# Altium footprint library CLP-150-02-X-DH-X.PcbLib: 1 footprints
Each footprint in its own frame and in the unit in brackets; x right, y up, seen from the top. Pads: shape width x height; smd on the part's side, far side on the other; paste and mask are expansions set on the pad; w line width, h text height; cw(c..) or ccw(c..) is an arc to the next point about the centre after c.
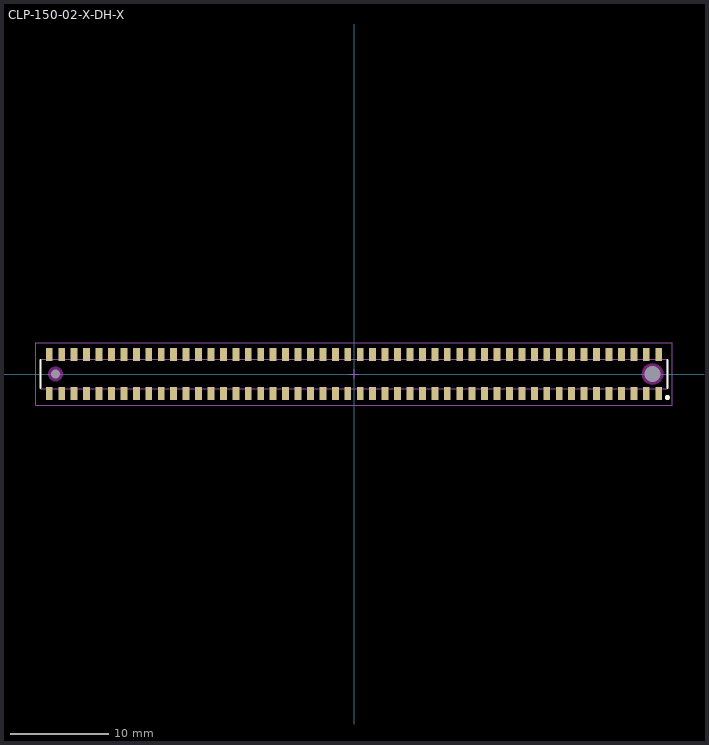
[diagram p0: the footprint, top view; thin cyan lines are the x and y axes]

## CLP-150-02-X-DH-X [mm] "1.27mm pitch, 100 pin, socket strip; low profile, vertical"
height 2.26
pads (102):
  rect 0.7x1.35 smd mask+0: 1(31.115,-1.99) 2(31.115,1.99) 3(29.845,-1.99) 4(29.845,1.99) 5(28.575,-1.99) 6(28.575,1.99) 7(27.305,-1.99) 8(27.305,1.99) 9(26.035,-1.99) 10(26.035,1.99) 11(24.765,-1.99) 12(24.765,1.99) 13(23.495,-1.99) 14(23.495,1.99) 15(22.225,-1.99) 16(22.225,1.99) 17(20.955,-1.99) 18(20.955,1.99) 19(19.685,-1.99) 20(19.685,1.99) 21(18.415,-1.99) 22(18.415,1.99) 23(17.145,-1.99) 24(17.145,1.99) 25(15.875,-1.99) 26(15.875,1.99) 27(14.605,-1.99) 28(14.605,1.99) 29(13.335,-1.99) 30(13.335,1.99) 31(12.065,-1.99) 32(12.065,1.99) 33(10.795,-1.99) 34(10.795,1.99) 35(9.525,-1.99) 36(9.525,1.99) 37(8.255,-1.99) 38(8.255,1.99) 39(6.985,-1.99) 40(6.985,1.99) 41(5.715,-1.99) 42(5.715,1.99) 43(4.445,-1.99) 44(4.445,1.99) 45(3.175,-1.99) 46(3.175,1.99) 47(1.905,-1.99) 48(1.905,1.99) 49(0.635,-1.99) 50(0.635,1.99) 51(-0.635,-1.99) 52(-0.635,1.99) 53(-1.905,-1.99) 54(-1.905,1.99) 55(-3.175,-1.99) 56(-3.175,1.99) 57(-4.445,-1.99) 58(-4.445,1.99) 59(-5.715,-1.99) 60(-5.715,1.99) 61(-6.985,-1.99) 62(-6.985,1.99) 63(-8.255,-1.99) 64(-8.255,1.99) 65(-9.525,-1.99) 66(-9.525,1.99) 67(-10.795,-1.99) 68(-10.795,1.99) 69(-12.065,-1.99) 70(-12.065,1.99) 71(-13.335,-1.99) 72(-13.335,1.99) 73(-14.605,-1.99) 74(-14.605,1.99) 75(-15.875,-1.99) 76(-15.875,1.99) 77(-17.145,-1.99) 78(-17.145,1.99) 79(-18.415,-1.99) 80(-18.415,1.99) 81(-19.685,-1.99) 82(-19.685,1.99) 83(-20.955,-1.99) 84(-20.955,1.99) 85(-22.225,-1.99) 86(-22.225,1.99) 87(-23.495,-1.99) 88(-23.495,1.99) 89(-24.765,-1.99) 90(-24.765,1.99) 91(-26.035,-1.99) 92(-26.035,1.99) 93(-27.305,-1.99) 94(-27.305,1.99) 95(-28.575,-1.99) 96(-28.575,1.99) 97(-29.845,-1.99) 98(-29.845,1.99) 99(-31.115,-1.99) 100(-31.115,1.99)
  round 0.5 hole 0.9 unplated mask+0: 101(-30.48,0)
  round 0.5 hole 1.65 unplated mask+0: 102(30.48,0)
Top Overlay:
  circle w0.25: c32,-2.4 r0.125
  lines w0.2: -32,-1.45 -32,1.45 ; 32,-1.45 32,1.45
Keep-Out Layer:
  pour cut-out: 31.589,0 31.552,0.287 31.441,0.555 31.265,0.785 31.035,0.961 30.767,1.072 30.48,1.109 30.193,1.072 29.925,0.961 29.695,0.785 29.519,0.555 29.408,0.287 29.371,0 29.408,-0.287 29.519,-0.555 29.695,-0.785 29.925,-0.961 30.193,-1.072 30.48,-1.109 30.767,-1.072 31.035,-0.961 31.265,-0.785 31.441,-0.555 31.552,-0.287
  pour cut-out: -29.724,0 -29.749,0.196 -29.825,0.378 -29.945,0.535 -30.102,0.655 -30.284,0.731 -30.48,0.756 -30.676,0.731 -30.858,0.655 -31.015,0.535 -31.135,0.378 -31.211,0.196 -31.236,0 -31.211,-0.196 -31.135,-0.378 -31.015,-0.535 -30.858,-0.655 -30.676,-0.731 -30.48,-0.756 -30.284,-0.731 -30.102,-0.655 -29.945,-0.535 -29.825,-0.378 -29.749,-0.196
Mechanical 12:
  lines w0.001: -32,-1.5 -32,1.5 32,1.5 32,-1.5 -32,-1.5
Mechanical 13:
  lines w0.1: -32,-1.5 -32,1.5 32,1.5 32,-1.5 -32,-1.5
  text ".Designator" at 0.254,0.254 h1.52
Mechanical 15:
  lines w0.05: -0.5,0 0.5,0 ; 0,-0.5 0,0.5 ; -32.487,-3.175 -32.487,3.175 32.487,3.175 32.487,-3.175 -32.487,-3.175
